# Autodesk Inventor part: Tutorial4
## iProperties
Shininess: 64.0
Length Units: 11269
Angle Units: 11279
Time Units: 11290
Mass Units: 11283
Length Display Precision: 3
Angle Display Precision: 2
Compacted: True
Part Number: Tutorial4
Document SubType Name: Modeling
Created: 2002-12
Designer: deepak
Density: 0.0
Volumn: 0.0
Area: 0.0
PropertySet Name: Model Information
Control State: 0
Master: False
Checked Out: False
Author: deepak
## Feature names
1. Revolution1
2. Chamfer2
